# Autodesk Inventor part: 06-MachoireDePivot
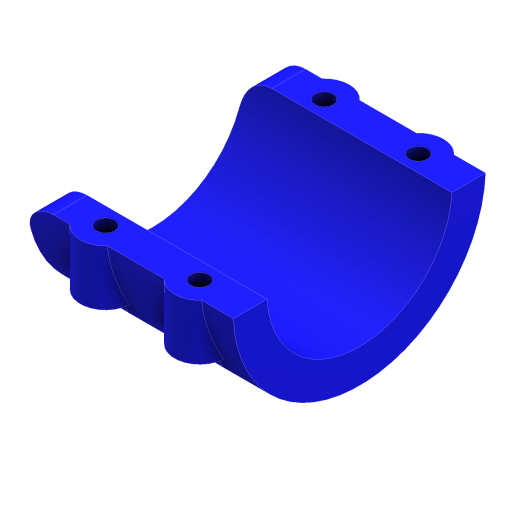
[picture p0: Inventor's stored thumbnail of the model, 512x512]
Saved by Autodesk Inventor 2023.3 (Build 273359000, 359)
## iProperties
Created: 2009-05
Part Number: 06-MachoireDePivot
Material: Générique
Document SubType Name: Modeling
Designer: Thier
Density: 1 g/cm^3
Appearance: Par défaut
Author: Thier
Sending System: SolidWorks 2008
Last Author: Roger
Last Saved: 2011-02-17
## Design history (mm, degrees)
feature "Enlèv. mat.-Extru.5"
node "Solide1"
